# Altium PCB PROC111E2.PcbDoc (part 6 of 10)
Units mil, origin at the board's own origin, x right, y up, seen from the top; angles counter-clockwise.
Board outline 7700 x 2300 mil, 6 copper layers (Top Layer, GND 1, SIG 1, SIG 2, GND 2, Bottom Layer), stack 78.711 mil thick; 767 components, 596 nets, 2755 pads, 1578 vias.
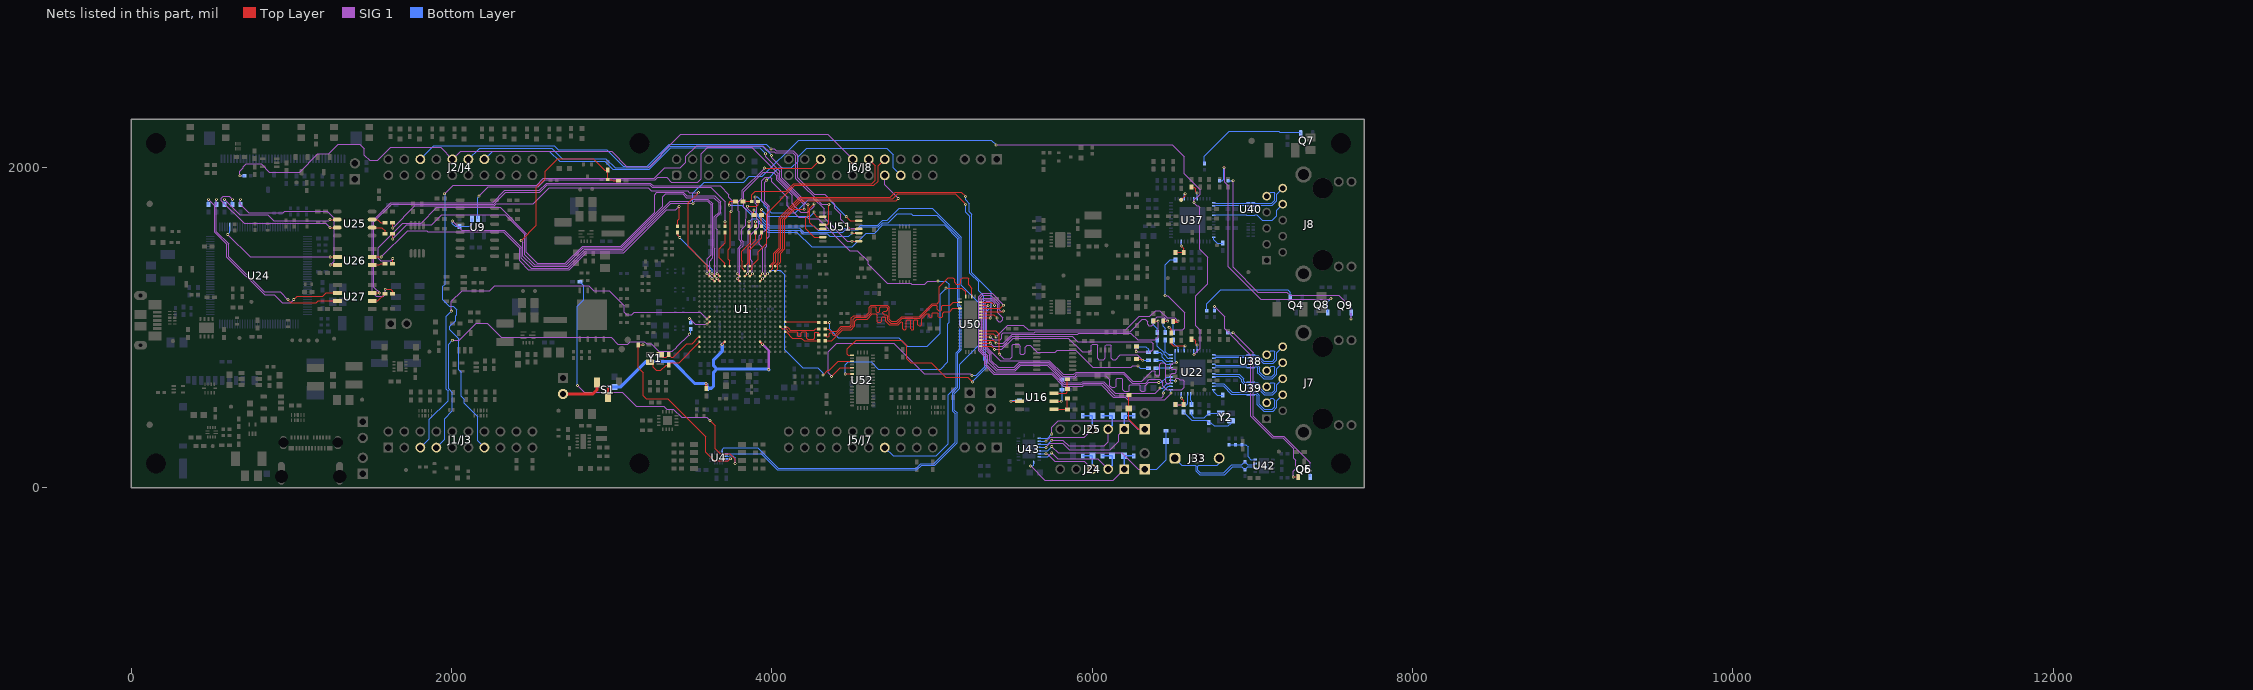
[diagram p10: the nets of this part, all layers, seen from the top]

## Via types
v1: diameter 18, hole 8, Top Layer to Bottom Layer, tented both sides, 1474 vias
v2: diameter 19.68, hole 7.87, Top Layer to Bottom Layer, tented both sides, 104 vias

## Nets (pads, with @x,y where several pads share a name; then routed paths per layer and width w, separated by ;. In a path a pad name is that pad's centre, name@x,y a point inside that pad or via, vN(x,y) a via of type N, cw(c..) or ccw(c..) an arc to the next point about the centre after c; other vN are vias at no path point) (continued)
AM263_RGMII1_TD2: R67.1 U50.25 | length 1428.5
  Top Layer w5.3: R67.1@4331.94,916.82 4373.56,916.82 4442.78,986.04 4494.62,986.04 4517.68,1009.1 4517.68,1039.31 4530.8,1052.44 4594.19,1052.44 4625.75,1084 4649.27,1084 4657.49,1075.78 4657.49,1036.99 4661.91,1032.57 4678.48,1032.57 4685,1039.09 4685,1059.57 4691.27,1065.83 4705.59,1065.83 4711.41,1060.02 4711.41,1038.55 4732.93,1017.03 4787.93,1017.03 4806.88,1035.98 4811.27,1035.98 4815.1,1032.15 4815.1,992.82 4821.94,985.98 4833.69,985.98 4838.47,990.75 4838.47,1040.1 4845,1046.63 4860,1046.63 4865,1041.63 4865,990.98 4870,985.98 4881.9,985.98 4885,989.08 4885,1041.63 4890,1046.63 4903.09,1046.63 4909.46,1040.27 4909.46,1018.34 4918.7,1009.1 4929.05,1009.1 4935.35,1015.4 4935.35,1054 4966.35,1085 4977.8,1085 4980.91,1081.9 4980.91,1066.49 4984.37,1063.04 4995.73,1063.04 5000.27,1067.58 5000.27,1087.35 5005,1092.09 5032.11,1092.09 5039.32,1084.88 5039.32,1067.71 5043.99,1063.04 5060,1063.04 5065.76,1068.79 5065.76,1089.06 5075.31,1098.62 5108.69,1098.62 5128.54,1118.46 U50.25@5173.43,1118.46
AM263_RGMII1_TD2_R: R67.2 U1.P18 | length 233.4
  Top Layer w5.3: U1.P18@4082.57,973.35 4087.82,973.35 4127.72,933.45 4184.23,933.45 4200.86,916.82 R67.2@4292.57,916.82
AM263_RGMII1_TD3: R68.1 U50.23 | length 1274
  Top Layer w5.3: R68.1@4331.94,952.82 4343.01,941.74 4352.79,941.74 4357.41,946.36 4357.41,961.57 4362.86,967.01 4374.36,967.01 4378.87,962.5 4378.87,955.3 4382.85,951.33 4393.08,951.33 4438.39,996.64 4490.22,996.64 4507.08,1013.49 4507.08,1051.3 4518.81,1063.04 4589.8,1063.04 4618.54,1091.78 4618.54,1122.48 4624.4,1128.34 4645,1128.34 4649.65,1123.69 4649.65,1100.31 4655.35,1094.6 4666.58,1094.6 4673.74,1101.76 4673.74,1122.08 4680,1128.34 4714.51,1128.34 4722.01,1120.84 4722.01,1110 4714.51,1102.5 4700,1102.5 4692.55,1095.05 4692.55,1087.55 4700.1,1080 4712.01,1080 4722.01,1070 4722.01,1046.11 4740.49,1027.63 4783.54,1027.63 4813.15,1057.23 4923.6,1057.23 5004.51,1138.15 5025,1138.15 5031.47,1131.67 5031.47,1113.66 5040.88,1104.25 5053.23,1104.25 5060,1111.03 5060,1133.15 5065,1138.15 5112.09,1138.15 5131.77,1157.83 U50.23@5173.43,1157.83
AM263_RGMII1_TD3_R: R68.2 U1.N17 | length 387.1
  Top Layer w4: U1.N17@4051.07,1004.84 4065.59,990.32
  Top Layer w5.3: 4065.59,990.32 4088.13,990.32 4105.96,972.49 4155,972.49 4161.05,966.45 4161.05,947.15 4164.15,944.05 4179.9,944.05 4183,947.15 4183,965.49 4190,972.49 4211.14,972.49 4218.5,965.14 4218.5,932.7 4223.78,927.42 4261.05,927.42 4268.07,934.44 4268.07,965.96 4271.18,969.06 4287.37,969.06 4292.57,963.87 R68.2@4292.57,952.82
AM263_RGMII1_TX_CTL: R69.1 U50.21 | length 1295
  Top Layer w5.3: R69.1@4331.94,1030.82 v1(4360,1030.82) ; v1(5087.15,1245.35) 5185.08,1245.35 5208.86,1221.57 U50.21@5208.86,1193.26
  Bottom Layer w5.3: v1(4360,1030.82) 4360,989.52 4414.52,935 4792.94,935 4845.53,882.4 4969.93,882.4 5050.6,963.07 5050.6,1208.8 v1(5087.15,1245.35)
AM263_RGMII1_TX_CTL_R: R69.2 U1.M18 | length 212.3
  Top Layer w5.3: U1.M18@4082.57,1036.34 4287.05,1036.34 R69.2@4292.57,1030.82
AM263_RGMII1_TXC: R70.1 U50.19 | length 1444
  Top Layer w5.3: R70.1@4331.94,989.82 4332.12,990 4355,990 4367.39,977.61 4404.37,977.61 4434,1007.24 4485.83,1007.24 4496.48,1017.88 4496.48,1059.94 4510.17,1073.64 4585.41,1073.64 4607.94,1096.17 4607.94,1127.68 4619.2,1138.94 4718.92,1138.94 4732.61,1125.25 4732.61,1050.5 4744.88,1038.23 4779.15,1038.23 4808.76,1067.83 4919.21,1067.83 5000.12,1148.75 5031.47,1148.75 5045.12,1162.4 5045.12,1255.39 5101.04,1311.31 5130,1311.31 5140.23,1301.08 5140.23,1282.14 5151.27,1271.09 5171.09,1271.09 5180,1280 5180,1301.31 5190,1311.31 5221.82,1311.31 5228.38,1304.75 5228.38,1266.01 5248.23,1246.17 U50.19@5248.23,1193.26
AM263_RGMII1_TXC_R: R70.2 U1.N18 | length 223
  Top Layer w4: U1.N18@4082.57,1004.84 4093.26,1004.84 4104.3,993.8
  Top Layer w5.3: 4104.3,993.8 4115,983.09 4264.3,983.09 4274.02,992.82 R70.2@4292.57,992.82
AM263_SAFETY_ERRORN: R258.1 R268.1 R272.1 U1.D4 | length 3081.6
  Top Layer w5.3: v1(2433.37,1542.21) 2529.29,1638.13 2529.29,1875.22 2583.47,1929.4 2583.47,1975.74 2661.47,2053.74 2884.26,2053.74 2956.06,1981.94 R258.1@2974.53,1981.94 2974.68,1981.79 R272.1@2974.68,1923.35 2975.04,1923.7 3000,1923.7 3008.24,1915.46 R268.1@3041.38,1915.46
  Top Layer w10: v1(3625.87,1304.06) U1.D4@3641.62,1288.31
  SIG 1 w4: 3610.87,1414.29 3610.87,1325.63 3625.87,1310.63 v1(3625.87,1304.06)
  SIG 1 w4.75: v1(2433.37,1542.21) 2445.05,1530.53 2445.05,1444.95 2509.04,1380.96 2724.9,1380.96 2831.89,1487.95 3064.45,1487.95 3365.07,1788.57 3489.88,1788.57 3502.41,1801.11 3600.33,1801.11 3630.27,1771.17 3630.27,1434.22 3610.87,1414.82 3610.87,1414.29
AM263_SD_ENABLE_GPIO122: U1.B16 U9.2 | length 3111.7
  Top Layer w4: U1.B16@4019.57,1351.3 4035.32,1367.05 4035.32,1390 4047.49,1402.17
  Top Layer w5.3: 4047.49,1402.17 4054.95,1409.63 4054.95,1464.39 4081.16,1490.6 4081.16,1675.53 4143.47,1737.85 v1(4201.68,1737.85)
  SIG 1 w4.75: v1(2170,1820) 2229.09,1879.09 2540.06,1879.09 2583.09,1922.12 3269.76,1922.12 3285.51,1937.87 3341.6,1937.87 3372.21,1907.27 3536.53,1907.27 3558.06,1928.8 3558.06,2085 3599.1,2126.04 3873.96,2126.04 4039.07,1960.93 4039.07,1927.47 4201.68,1764.86 v1(4201.68,1737.85)
  Bottom Layer w5.3: U9.2@2163.97,1678.43 2163.97,1810.55 2170,1816.58 v1(2170,1820)
AM263_SDFM0_CLK1: J6/J8.74 U1.A16 | length 1267.7
  Top Layer w5.3: U1.A16@4019.57,1382.8 4019.57,1387.4 4040,1407.83 4040,1464.43 4066.16,1490.59 4066.16,1675.52 4183,1792.36 4775.51,1792.36 v1(4788.5,1805.35)
  SIG 1 w5.3: J6/J8.74@4704.17,1950 4704.17,1889.68 v1(4788.5,1805.35)
AM263_SDFM0_CLK2: U1.B15 U52.26 | length 4090.4
  Top Layer w4: U1.B15@3988.08,1351.3 4005.7,1368.92 4005.7,1392.42 4015,1401.72
  Top Layer w5.3: 4015,1401.72 4025,1411.72 4025,1464.42 4055.56,1494.98 4055.56,1679.91 4178.61,1802.96 4752.96,1802.96 4784.76,1834.76 5143.4,1834.76 v1(5209.51,1768.66) ; v1(4372.19,693.86) 4372.19,696.09 4424.84,748.74 U52.26@4500.04,748.74
  SIG 1 w4.75: v1(4372.19,693.86) 4350,716.05 4350,849.04 4402.89,901.93 4760.56,901.93 4952,710.49 5237.09,710.49 5247.57,700 v1(5249.4,700)
  Bottom Layer w5.3: v1(5209.51,1768.66) 5209.51,1718.49 5234,1694 5234,1340.01 5290.12,1283.89 5290.12,1230.61 5322.88,1197.86 5322.88,795.76 5330,788.64 5330,754.57 5275.43,700 v1(5249.4,700)
AM263_SDFM0_CLK3: U1.A15 U52.22 | length 3872.2
  Top Layer w5.3: U1.A15@3988.08,1382.8 3988.08,1387.95 4010,1409.87 4010,1464.41 4044.35,1498.76 4044.35,1683.69 4174.22,1813.56 4738.56,1813.56 4770.36,1845.36 5182.8,1845.36 v1(5209.51,1818.66) ; U52.22@4500.04,827.48 4477.74,827.48 4471.48,833.74 4471.48,867.38 4525.54,921.45 4806.49,921.45 4842.94,885 4842.94,803.2 4867.11,779.03 4995.61,779.03 5084.52,690.11 5221.46,690.11 v1(5251.57,660)
  Bottom Layer w5.3: v1(5209.51,1818.66) 5209.51,1796.49 5232,1774 5232,1721.5 5247,1706.5 5247,1342 5369.52,1219.48 5369.52,1130.06 5333.48,1094.01 5333.48,800.15 5342.59,791.03 5342.59,751.02 v1(5251.57,660)
AM263_SDFM0_D2: U1.C13 U52.28 | length 3448.3
  Top Layer w5.3: v1(4457.78,709.37) U52.28@4500.04,709.37
  Top Layer w10: U1.C13@3925.09,1319.8 v1(3940.83,1335.55)
  SIG 1 w4: v1(3940.83,1335.55) 3940.83,1414.29
  SIG 1 w4.75: 3940.83,1414.29 3940.83,1499.17 3921.5,1518.5 3921.5,1571.78 3973.56,1623.84 3973.56,1752.64 3935.25,1790.95 3935.25,1915.6 3958.91,1939.25 3989.67,1939.25 3998.88,1930.04 3998.88,1909.72 4095.91,1812.69 4095.91,1759.11 4166.58,1688.45 4218.83,1688.45 4229.7,1677.58 4288.57,1677.58 4486.15,1480 4532.78,1480 4600.1,1412.68 4600.1,1395.57 4718.89,1276.77 4865.99,1276.77 4873.45,1269.3 4954.28,1269.3 4974.03,1289.06 v1@5036.55,1289.06
  Bottom Layer w5.3: v1(4457.78,709.37) 4457.78,766.95 4475.83,785 4619.38,785 4663.91,740.48 5053.89,740.48 5098.42,785 5098.42,1023.75 5106.67,1032.01 5106.67,1268.33 5085.59,1289.41 v1(5036.55,1289.41)
AM263_SDFM0_D3: U1.C14 U52.24 | length 1145.3
  Top Layer w5.3: v1(4318.59,702.78) 4349.11,733.31 4357.41,733.31 4412.22,788.11 U52.24@4500.04,788.11
  Top Layer w10: U1.C14@3956.58,1319.8 v1(3972.33,1335.55)
  Bottom Layer w5.3: v1(3972.33,1335.55) 3992.66,1355.88 4052.2,1355.88 4080.23,1327.84 4080.23,859.61 4191.46,748.38 4284.58,748.38 4318.59,714.37 v1(4318.59,702.78)
AM263_SFDM0_D1: J6/J8.73 U1.D13 | length 1729.1
  Top Layer w10: U1.D13@3925.09,1288.31 v1(3940.83,1304.06)
  SIG 1 w4: v1(3940.83,1304.06) 3957.33,1320.55 3957.33,1414.29
  SIG 1 w4.75: 3957.33,1414.29 3957.33,1496.33 3968,1507 3968,1554.28 3983.61,1569.89 3983.61,1756.81 3955,1785.42 3955,1908.12 v1(3966.88,1920)
  Bottom Layer w5.3: v1(3966.88,1920) 4042.66,1995.78 4121.38,1995.78 4163.14,2037.54 4163.14,2067 4216.01,2119.88 4717.44,2119.88 4757.29,2080.03 4757.29,1996.89 J6/J8.73@4804.17,1950
AM263_SOP0: R42.2 U4.15 | length 1162.8
  Top Layer w5.3: v1(3195,891.81) 3194.37,891.17 R42.2@3164.53,891.17 3164.53,748.79 3196.58,716.74 3196.58,573.42 3214.36,555.64 3348.26,555.64 3587.63,316.27 3587.63,219.09 3640,166.73 3726.88,166.73 v1(3740.06,179.91)
  Bottom Layer w5.3: U4.15@3713.32,179.91 v1(3740.06,179.91)
AM263_SOP1: R43.2 U4.14 | length 2060.4
  Top Layer w5.3: v1(3613.09,418.7) 3645.4,386.39 3645.4,243.33 3676.8,211.93 3735.65,211.93 3770,177.58 v1(3770,150)
  SIG 1 w4.75: v1(2785,638.11) 2828.96,594.15 3065,594.15 3151.87,507.27 3324.67,507.27 3342.27,489.68 3383.59,489.68 3435.04,438.22 3593.57,438.22 v1(3613.09,418.7)
  Bottom Layer w5.3: v1(2785,638.11) 2785,1131.61 2825,1171.61 2825,1260.61 R43.2@2800.61,1285 ; U4.14@3713.32,195.65 3728.2,195.65 3731.98,199.43 3756.37,199.43 3770,185.8 v1(3770,150)
AM263_SOP2: R173.2 U4.13 | length 4461.5
  Top Layer w5.3: R173.2@3886.97,1702.62 v1(3886.97,1733.21)
  Bottom Layer w5.3: U4.13@3713.32,211.4 3932.67,211.4 4034.07,110 4904.98,110 4934.38,139.4 5015.09,139.4 5155.35,279.65 5155.35,467.78 5138.73,484.4 5138.73,586.24 5171.62,619.13 5171.62,769.83 5289.73,887.94 5289.73,1153.66 5180.96,1262.44 5180.96,1564.13 5001.7,1743.39 4793.41,1743.39 4719.52,1669.5 4691.53,1669.5 4660.68,1638.65 4553.42,1638.65 4534.43,1619.65 4451.52,1619.65 4438.06,1606.19 4288.81,1606.19 4260.37,1634.64 3985.54,1634.64 v1(3886.97,1733.21)
AM263_SOP3: R174.2 U4.12 | length 4581.4
  Top Layer w5.3: v1(3733.14,1763.52) 3733.14,1779.8 3740,1786.65 R174.2@3771.82,1786.65
  Bottom Layer w5.3: U4.12@3689.69,219.28 3689.69,237.41 3699.69,247.41 3911.66,247.41 4038.46,120.6 4900.59,120.6 4929.99,150 5010,150 5144.52,284.52 5144.52,460.48 5128.13,476.87 5128.13,592.84 5160.6,625.31 5160.6,838.49 5183.1,860.98 5183.1,1125.25 5170.36,1137.99 5170.36,1559.74 5030.22,1699.88 4878.64,1699.88 4869,1709.52 4783.02,1709.52 4727,1653.5 4690.53,1653.5 4665.07,1628.05 4557.81,1628.05 4538.82,1609.05 4455.91,1609.05 4442.46,1595.59 4197.76,1595.59 4169.31,1624.04 3981.15,1624.04 3905.78,1699.41 3875.08,1699.41 3810.96,1763.52 v1(3733.14,1763.52)
AM263_SPI0_CLK: R169.1 R173.1 U51.2 | length 534.3
  Top Layer w5.3: v1(3934.21,1736.34) R173.1@3934.21,1702.62 3934.21,1632.95 R169.1@3935,1632.17 ; v1(4263.16,1720.73) 4263.16,1708.73 4280,1691.89 U51.2@4317.8,1691.89
  Bottom Layer w5.3: v1(3934.21,1736.34) 3974.91,1695.64 4238.07,1695.64 v1(4263.16,1720.73)
AM263_SPI0_CLK_PR0_PRU0_GPIO16: J1/J3.7 U51.4 | length 4690.4
  Top Layer w5.3: U51.4@4317.8,1640.71 4345.71,1640.71 4355,1650 v1(4355,1768.66)
  SIG 1 w4.75: v1(1954,1835) 1955.43,1835 2009.57,1889.14 2529.38,1889.14 2572.41,1932.17 3265.59,1932.17 3330.65,1997.22 3426.04,1997.22 3461.44,2032.63 3461.44,2067.7 3529.84,2136.09 3942.04,2136.09 3981.91,2096.22 4013.46,2096.22 4018.92,2090.76 4130.41,2090.76 4149.68,2071.49 4149.68,1929.92 4310.93,1768.66 v1(4355,1768.66)
  Bottom Layer w5.3: v1(1954,1835) 1958.18,1830.82 1958.18,1270.03 1944.52,1256.37 1944.52,1172.03 1984.79,1131.77 2010.16,1131.77 2030,1111.93 2030,1079.5 2024.06,1073.56 2024.06,1042.47 1988.42,1006.83 1988.42,985.61 2045.25,928.79 2045.25,736.04 2059.88,721.42 2059.88,570.48 2079.28,551.08 2079.28,526.21 2163.14,442.35 2163.14,291.04 J1/J3.7@2204.17,250
AM263_SPI0_CLK_R: R169.2 U1.A11 | length 240.2
  Top Layer w5.3: U1.A11@3862.09,1382.8 3862.09,1485.78 3935,1558.69 R169.2@3935,1592.8
AM263_SPI0_CS0: U1.C11 U51.14 | length 1317.9
  Top Layer w5.3: v1(4464,1691.89) 4489.59,1666.3 U51.14@4542.2,1666.3
  Top Layer w10: U1.C11@3862.09,1319.8 v1(3877.84,1335.55)
  SIG 1 w4: 3874.64,1414.29 3877.84,1411.09 v1(3877.84,1335.55)
  SIG 1 w4.75: 3874.64,1414.29 3866.86,1422.07 3866.86,1578.09 3916.25,1627.48 3916.25,1668.2 3906.22,1678.23 3906.22,1764.48 3894.94,1775.76 v1(3894.94,1815)
  Bottom Layer w5.3: v1(3894.94,1815) 3908.2,1815 3952.04,1771.17 3952.04,1761.12 3996.08,1717.08 4145.81,1717.08 4227.4,1798.67 4357.21,1798.67 v1(4464,1691.89)
AM263_SPI0_CS0_PR0_PRU0_GPIO8: J2/J4.18 U51.12 | length 3218.3
  Top Layer w5.3: v1(4464,1640.71) 4489.59,1615.12 U51.12@4542.2,1615.12
  SIG 1 w4.75: 4330.46,1830.85 4391.5,1769.82 4391.5,1745.5 4429.7,1707.3 4429.7,1675 v1(4464,1640.71)
  SIG 1 w5.3: v1(3993.13,2115.47) 4014.1,2115.47 4026.74,2102.83 4132.94,2102.83 4160,2075.77 4160,1934.19 4263.34,1830.85 4330.46,1830.85
  Bottom Layer w5.3: J2/J4.18@1804.17,2050 1889.17,2135 2640,2135 2665.89,2109.11 2969.11,2109.11 3070.33,2007.89 3222.13,2007.89 3359.23,2145 3963.61,2145 v1(3993.13,2115.47)
AM263_SPI0_D0: J6/J8.55 R170.1 R174.1 | length 1053.4
  Top Layer w5.3: R174.1@3819.07,1786.65 R170.1@3873.62,1786.65 3873.62,1828.88 3896.6,1851.85 4089.3,1851.85 4135.81,1898.36 4624.12,1898.36 4645.21,1919.45 4645.21,2008.96 J6/J8.55@4604.17,2050
AM263_SPI0_D0_R: R170.2 U1.C10 | length 559.8
  Top Layer w5.3: v1(3846.35,1756.91) 3904.46,1756.91 3912.99,1765.44 R170.2@3912.99,1786.65
  Top Layer w10: U1.C10@3830.6,1319.8 v1(3846.35,1335.55)
  SIG 1 w4: v1(3846.35,1335.55) 3846.35,1339.14 3850.91,1343.7 3850.91,1414.29
  SIG 1 w4.75: v1(3846.35,1756.91) 3846.35,1745 3876.25,1715.1 3876.25,1631.94 3850.91,1606.6 3850.91,1414.29
AM263_SPI0_D1: J6/J8.54 U1.B11 | length 1336.4
  Top Layer w4: U1.B11@3862.09,1351.3 3876.62,1365.82
  Top Layer w5.3: 3876.62,1365.82 3876.62,1389.62 3913.25,1426.24 3913.25,1472.59 3966.88,1526.23 3966.88,1711.16 4143.48,1887.76 4636.7,1887.76 4663.14,1914.2 4663.14,2008.96 J6/J8.54@4704.17,2050
AM263_SPI1_CLK: J5/J7.47 R171.1 | length 3214.5
  Top Layer w5.3: R171.1@3897,1632.17 v1(3897,1660.23)
  Bottom Layer w5.3: v1(3897,1660.23) 3909.62,1660.23 3974.99,1594.86 4155,1594.86 4247.08,1502.78 4501.02,1502.78 4587.24,1589 4641.02,1589 4692.87,1640.85 5074.26,1640.85 5159.76,1555.35 5159.76,1133.6 5172.5,1120.86 5172.5,865.37 5150,842.88 5150,630.01 5100,580.01 5100,272.8 5025.56,198.36 4755.81,198.36 J5/J7.47@4704.17,250
AM263_SPI1_CLK_R: R171.2 U1.A10 | length 237.5
  Top Layer w5.3: U1.A10@3830.6,1382.8 3851.19,1403.38 3851.19,1497.25 3897,1543.06 R171.2@3897,1592.8
AM263_SPI1_CS0: J6/J8.58 U1.C9 | length 1141.1
  Top Layer w5.3: v1(3953.46,1995.18) 4249.35,1995.18 J6/J8.58@4304.17,2050
  Top Layer w10: v1(3783.35,1335.55) U1.C9@3799.1,1319.8
  SIG 1 w4: v1(3783.35,1335.55) 3783.35,1339.14 3788.3,1344.09 3788.3,1414.29
  SIG 1 w4.75: 3788.3,1414.29 3788.3,1494.61 3809.25,1515.55 3809.25,1531.5 3794.5,1546.25 3794.5,1724.62 3790.75,1728.37 3790.75,1785.31 3814.95,1809.51 3814.95,1856.66 v1(3953.46,1995.18)
AM263_SPI1_D0: R172.1 U51.11 | length 776.2
  Top Layer w5.3: R172.1@3857,1632.17 v1(3857,1660.23) ; v1(4500,1589.53) U51.11@4542.2,1589.53
  Bottom Layer w5.3: v1(3857,1660.23) 3876.52,1679.75 3905.09,1679.75 3979.38,1605.46 4172.9,1605.46 4193.37,1584.99 4345,1584.99 4361.53,1568.46 4478.94,1568.46 v1(4500,1589.53)
AM263_SPI1_D0_PR0_PRU0_GPIO13: J2/J4.15 U51.9 | length 2897.4
  Top Layer w5.3: v1(4500,1538.35) U51.9@4542.2,1538.35
  SIG 1 w5.3: v1(3997.52,2074.18) 3997.52,2060.69 4060,1998.21 4060,1936.14 4185.98,1810.16 4254.83,1810.16 4325.26,1739.73 4325.26,1683.91 4470.83,1538.35 v1(4500,1538.35)
  Bottom Layer w5.3: J2/J4.15@2104.17,2050 2174.17,2120 2625,2120 2690,2055 2962.39,2055 3020.09,1997.29 3226.52,1997.29 3361.68,2132.45 3940.18,2132.45 3997.52,2075.11 v1(3997.52,2074.18)
AM263_SPI1_D0_R: R172.2 U1.B10 | length 274
  Top Layer w4: 3812.98,1414.29 3812.98,1368.92 U1.B10@3830.6,1351.3
  Top Layer w5.3: 3812.98,1414.29 3812.14,1415.13 3812.14,1475.98 3864.6,1528.44 3864.6,1585.2 R172.2@3857,1592.8
AM263_SPI1_D1: U1.D9 U51.5 | length 1498.9
  Top Layer w5.3: v1(4263.16,1771.81) 4236.08,1744.72 4236.08,1654.63 4275.59,1615.12 U51.5@4317.8,1615.12
  Top Layer w10: v1(3783.35,1304.06) U1.D9@3799.1,1288.31
  SIG 1 w4: v1(3783.35,1304.06) 3798.35,1319.06 3798.35,1414.29
  SIG 1 w4.75: 3798.35,1414.29 3798.35,1490.45 3819.3,1511.39 3819.3,1535.66 3810,1544.96 3810,1612 3835.5,1637.5 3835.5,1676 3840,1680.5 3840,1736.03 3825,1751.03 3825,1847.98 3946.42,1969.4 4007.1,1969.4 4029.02,1947.47 4029.02,1922.21 4126.06,1825.18 4126.06,1771.6 4179.07,1718.6 4224.16,1718.6 4263.16,1757.6 v1(4263.16,1771.81)
AM263_SPI1_D1_PR0_PRU0_GPIO14: J2/J4.14 U51.7 | length 2617.5
  Top Layer w5.3: v1(4225,1768.66) 4225,1699.19 4209.47,1683.66 4209.47,1617.63 4263.16,1563.94 U51.7@4317.8,1563.94
  SIG 1 w4.75: 4139.62,1841.52 4212.49,1768.66 v1(4225,1768.66)
  SIG 1 w5.3: v1(3960,2085) 3960,2065.82 4049.4,1976.43 4049.4,1931.75 4139.62,1841.52
  Bottom Layer w5.3: J2/J4.14@2204.17,2050 2255.81,2101.64 2608.36,2101.64 2673.33,2036.67 2955.83,2036.67 3005.81,1986.69 3233.69,1986.69 3368.85,2121.85 3923.15,2121.85 v1(3960,2085)
AM263_TCK: R324.1 U1.B3 | length 2631.6
  Top Layer w4: 3562.54,1418.51 3594.38,1386.67 3594.38,1367.05 U1.B3@3610.12,1351.3
  Top Layer w5.3: v1(1631.5,1620.83) R324.1@1631.5,1653.35 ; v1(3541.39,1842.03) 3476.63,1777.28 3476.63,1506.42 3562.54,1420.52 3562.54,1418.51
  SIG 1 w4.75: v1(1631.5,1620.83) 1770.28,1759.61 2265.99,1759.61 2278.18,1771.81 2508.64,1771.81 2608.7,1871.87 3228.06,1871.87 3246.19,1853.74 3472.88,1853.74 3484.59,1842.03 v1(3541.39,1842.03)
AM263_TCK_R: R324.2 U25.7 | length 90.4
  Top Layer w5.3: U25.7@1502.36,1673.86 1536.44,1673.86 1556.95,1653.35 R324.2@1584.25,1653.35
AM263_TCK_XDS: R133.1 U25.2 | length 795.1
  Top Layer w5.3: v1(1240,1673.86) U25.2@1285.36,1673.86
  SIG 1 w4.75: v1(580.73,1800) 675.73,1705 851.3,1705 889.42,1666.88 1233.02,1666.88 v1(1240,1673.86)
  Bottom Layer w5.3: R133.1@580.5,1767.63 580.5,1799.77 v1(580.73,1800)
AM263_TDI: R326.1 U1.C5 | length 3414.3
  Top Layer w5.3: R326.1@1631.5,1398.01 v1(1631.5,1430.54)
  Top Layer w10: v1(3657.37,1335.55) U1.C5@3673.12,1319.8
  SIG 1 w4: v1(3657.37,1335.55) 3657.37,1414.29
  SIG 1 w4.75: v1(1631.5,1430.54) 1618.09,1417.13 1555.65,1417.13 1540.75,1432.03 1540.75,1497.97 1692.9,1650.12 1808.12,1650.12 1907.56,1749.56 2301.91,1749.56 2465.15,1586.32 2465.15,1469.32 2533.41,1401.06 2710.03,1401.06 2817.47,1508.5 3055.8,1508.5 3267.56,1720.26 3267.56,1830 3281.25,1843.69 3445.5,1843.69 3467.99,1821.21 3641.7,1821.21 3679.24,1783.66 3679.24,1716.73 3650.37,1687.85 3650.37,1617.16 3657.37,1610.16 3657.37,1414.29
AM263_TDI_R: R326.2 U26.2 | length 84.3
  Top Layer w5.3: U26.2@1503.27,1390 1548.12,1390 1556.13,1398.01 R326.2@1584.25,1398.01
AM263_TDI_XDS: R135.1 U26.7 | length 1038.9
  Top Layer w5.3: v1(1241.37,1390) U26.7@1286.73,1390
  SIG 1 w4.75: v1(680.73,1800) 680.73,1767.91 733.03,1715.6 948.67,1715.6 957.59,1724.52 1222.37,1724.52 1265,1681.9 1265,1413.63 v1(1241.37,1390)
  Bottom Layer w5.3: R135.1@680.5,1767.63 680.5,1799.77 v1(680.73,1800)
AM263_TDO: R7.2 U26.3 | length 2423.5
  Top Layer w5.3: U26.3@1503.27,1440 v1(1560,1440) ; R7.2@3410,1632.17 3410,1668.5 3420,1678.5 v1(3420,1755.5)
  SIG 1 w4.75: v1(1560,1440) 1724.56,1604.56 1842.76,1604.56 1850,1597.32 2320.9,1597.32 2423.42,1494.8 2423.42,1415.12 2477.68,1360.86 2733.22,1360.86 2840.12,1467.76 3073.26,1467.76 3341.5,1736 3400.5,1736 v1(3420,1755.5)
AM263_TDO_R: R7.1 U1.C4 | length 368.9
  Top Layer w5.3: R7.1@3410,1592.8 3410.06,1592.74 3410.06,1576.14 v1(3424.12,1562.07)
  Top Layer w10: v1(3625.87,1335.55) U1.C4@3641.62,1319.8
  Bottom Layer w4: 3570.71,1414.29 3625.87,1359.13 v1(3625.87,1335.55)
  Bottom Layer w5.3: v1(3424.12,1562.07) 3424.12,1560.88 3570.71,1414.29
AM263_TDO_XDS: U24.37 U26.6 | length 796.7
  Top Layer w5.3: v1(1241.37,1440) U26.6@1286.73,1440
  SIG 1 w4.75: v1(601.14,1579.87) 741.01,1440 v1(1241.37,1440)
  Bottom Layer w5.3: v1(601.14,1579.87) 614.4,1593.13 U24.37@614.4,1627.52
AM263_TEMPCAL: U1.U1
AM263_TMS: R325.1 U1.D5 | length 3093.5
  Top Layer w5.3: v1(1631.5,1552.4) R325.1@1631.5,1584.92
  Top Layer w10: v1(3657.37,1304.06) U1.D5@3673.12,1288.31
  SIG 1 w4: 3642.37,1414.29 3642.37,1319.06 v1(3657.37,1304.06)
  SIG 1 w4.75: v1(1631.5,1552.4) 1719.17,1640.07 1874.63,1640.07 1936.81,1702.26 2335,1702.26 2455.1,1582.16 2455.1,1454.9 2518.99,1391.01 2714.2,1391.01 2821.64,1498.45 3059.96,1498.45 3319.02,1757.5 3319.02,1817.65 3335.01,1833.64 3441.34,1833.64 3463.83,1811.16 3637.53,1811.16 3669.19,1779.5 3669.19,1720.89 3640.32,1692.02 3640.32,1493.54 3642.37,1491.49 3642.37,1414.29
AM263_TMS_R: R325.2 U25.6 | length 109.2
  Top Layer w5.3: U25.6@1502.36,1623.86 1564.43,1623.86 1584.25,1604.05 R325.2@1584.25,1584.92
AM263_TMS_XDS: R134.1 U25.3 | length 925.6
  Top Layer w5.3: v1(1240,1623.86) U25.3@1285.36,1623.86
  SIG 1 w4.75: v1(630.73,1800) 610.73,1820 573.12,1820 560.7,1807.58 560.7,1792.42 703.12,1650 1213.86,1650 v1(1240,1623.86)
  Bottom Layer w5.3: R134.1@630.5,1767.63 630.5,1799.77 v1(630.73,1800)
AM263_UART0_RXD: R327.1 U1.A7 | length 3464
  Top Layer w4: U1.A7@3736.11,1382.8 3736.11,1414.29
  Top Layer w5.3: v1(1585,1238.85) 1618.09,1238.85 1631.5,1225.45 R327.1@1631.5,1210 ; 3736.11,1414.29 3736.11,1416.7 3726.25,1426.56 3726.25,1486.51 3740,1500.26 3740,1720 v1(3745,1725)
  SIG 1 w4.75: v1(1585,1238.85) 1585,1207.95 1573.07,1196.02 1529.25,1196.02 1503.89,1221.38 1503.89,1664.49 1619.11,1779.71 2255.44,1779.71 2332.59,1856.87 2546.9,1856.87 2592.05,1902.02 3240.56,1902.02 3257.48,1885.1 3675.32,1885.1 3730.75,1829.67 3730.75,1814.12 3752.39,1792.48 3752.39,1732.39 v1(3745,1725)
AM263_UART0_RXD_R: R327.2 U27.2 | length 99.5
  Top Layer w5.3: U27.2@1503.27,1165.27 1539.52,1165.27 R327.2@1584.25,1210
AM263_UART0_RXD_XDS: R131.1 U27.7 | length 1225
  Top Layer w5.3: v1(977.49,1173.93) 997.33,1154.09 1155,1154.09 ; 1155,1154.4 1155.32,1154.4 1166.18,1165.27 U27.7@1286.73,1165.27
  SIG 1 w4.75: v1(530.73,1800) 530.73,1598.86 607.1,1522.49 607.1,1442.9 828.18,1221.82 929.6,1221.82 v1(977.49,1173.93)
  Bottom Layer w5.3: R131.1@530.5,1767.63 530.5,1799.77 v1(530.73,1800)
AM263_UART0_TXD: R164.1 U27.3 | length 2991.7
  Top Layer w5.3: U27.3@1503.27,1215.27 v1(1550,1215.27) ; R164.1@3707,1632.17 v1(3707,1660.23)
  SIG 1 w4.75: v1(1550,1215.27) 1513.94,1251.33 1513.94,1658.94 1624.66,1769.66 2261.82,1769.66 2336.41,1844.25 2548.49,1844.25 2596.21,1891.97 3236.4,1891.97 3253.32,1875.05 3616.28,1875.05 3707,1784.33 v1(3707,1660.23)
AM263_UART0_TXD_R: R164.2 U1.A6 | length 241.4
  Top Layer w5.3: U1.A6@3704.61,1382.8 3704.61,1400.18 3669.34,1435.45 3669.34,1490.02 3708.39,1529.07 3708.39,1591.41 R164.2@3707,1592.8
AM263_UART0_TXD_XDS: R129.1 U27.6 | length 1275
  Top Layer w5.3: v1(1013.7,1173.93) 1035.48,1195.71 1195.71,1195.71 1215.27,1215.27 U27.6@1286.73,1215.27
  SIG 1 w4.75: v1(480.73,1800) 520.13,1760.6 520.13,1594.47 596.5,1518.1 596.5,1438.51 831.18,1203.83 891.41,1203.83 940.83,1154.41 994.18,1154.41 v1(1013.7,1173.93)
  Bottom Layer w5.3: R129.1@480.5,1767.63 480.5,1799.77 v1(480.73,1800)
AM263_UART1_RXD: J1/J3.3 U1.L3 | length 2783.2
  Top Layer w10: v1(3594.38,1052.09) U1.L3@3610.12,1067.83
  SIG 1 w4.75: v1(1997.69,1101.65) 1997.69,1162.66 2064.46,1229.44 2237.21,1229.44 2268.14,1260.36 2855.42,1260.36 2887.28,1228.5 2984.8,1228.5 3078.21,1135.09 3078.21,1095 3093.21,1080 3125.39,1080 3140.39,1095 3551.46,1095 v1(3594.38,1052.09)
  Bottom Layer w5.3: J1/J3.3@1804.17,250 1860,305.83 1860,426.72 1976.8,543.51 1976.8,604.62 1966.24,615.18 1966.24,1070.2 v1(1997.69,1101.65)
AM263_UART1_TXD: J1/J3.4 R165.1 | length 2422
  SIG 1 w4.75: v1(2004.02,919.76) 2045.73,919.76 2152.38,1026.42 2221.36,1026.42 2309.83,937.95 2995.7,937.95 3038.23,895.42 3097.69,895.42 3113.32,911.06 3202.97,911.06 3216.83,897.2 3246.37,897.2 3292.87,850.7 3378.14,850.7 3405.31,877.88 3405.31,878.5 v1(3485,958.19)
  Bottom Layer w5.3: J1/J3.4@1904.17,250 1955,300.83 1955,431.22 2004.54,480.76 2004.54,591.87 1980.4,616.02 1980.4,896.14 v1(2004.02,919.76) ; v1@3485,957.6 3492.19,964.79 R165.1@3492.19,989.72
AM263_UART1_TXD_R: R165.2 U1.M3 | length 177.1
  Top Layer w10: v1(3594.38,1020.59) U1.M3@3610.12,1036.34
  SIG 1 w5.3: v1(3484.5,1056.16) 3520.07,1020.59 v1(3594.38,1020.59)
  Bottom Layer w5.3: v1(3484.5,1056.16) 3492.19,1048.47 R165.2@3492.19,1029.09
AM263_WARMRSTN: R5.2 U1.C3 U9.1 U22.43 U37.43 | length 7360.7
  Top Layer w10: v1(3594.38,1335.55) U1.C3@3610.12,1319.8
  SIG 1 w4: v1(3594.38,1335.55) 3594.38,1408.67
  SIG 1 w4.75: v1(2004.02,1665) 2061.65,1607.37 2327.48,1607.37 2435,1499.85 2435,1432.68 2496.77,1370.91 2729.06,1370.91 2835.96,1477.81 3069.1,1477.81 3366.29,1775 v1(3506.1,1775) 3522.16,1791.06 3596.17,1791.06 3620.22,1767 3620.22,1453.81 3594.38,1427.97 3594.38,1408.67 ; v1(5400,2140) 6500,2140 6575,2065 6575,1960.02 6674.25,1860.77 6674.25,1832.03 6635.02,1792.8 v1(6635.02,1779.98) 6654,1761 6660.47,1761 6672.23,1749.23 6672.23,1488.26 6721.09,1439.41 6721.09,1271.92 6646.97,1197.79 6646.97,1010.2 6674.25,982.92 6674.25,869.21 v1(6635.02,829.98)
  Bottom Layer w5.3: v1(2004.02,1665) 2004.02,1648.05 2021.02,1631.04 R5.2@2048.11,1631.04 2111.04,1631.04 2126.56,1646.56 U9.1@2126.56,1678.43 ; v1(3506.1,1775) 3506.1,1837.38 3575.71,1907 3823.22,1907 3859.52,1943.29 3939.43,1943.29 4165.66,2169.52 5370.48,2169.52 v1(5400,2140) ; v1(6635.02,829.98) U22.43@6635.02,853.9 ; v1(6635.02,1779.98) U37.43@6635.02,1803.9
AM263_XTAL_XI: C58.1 U1.T1 Y1.1 | length 416.1
  Top Layer w5.3: Y1.1@3238.01,782.59 3242.89,782.59 3256.98,768.51 3256.98,751.63 3276.91,731.69 3305.48,731.69 3338.34,764.56 3354.72,764.56 C58.1@3355,764.84 3369.27,779.1 3419.37,779.1 3547.13,906.87 U1.T1@3547.13,910.35
AM263_XTAL_XO: C59.1 U1.R1 Y1.3 | length 317.9
  Top Layer w5.3: Y1.3@3301.99,829.84 3317.42,814.4 3338.69,814.4 C59.1@3355,830.71 3371.4,814.32 3383.73,814.32 3467.98,898.57 3500.62,898.57 3539.63,937.58 3542.86,937.58 U1.R1@3547.13,941.85
BP_PORZ: J2/J4.16 J6/J8.56 R180.2 | length 4344.6
  SIG 1 w4.75: v1(677.39,1947.24) 677.39,1974.61 699.25,1996.47 699.25,2005 716.59,2022.34 809.83,2022.34 861.41,1970.75 1051.07,1970.75 1164.32,2084 1232.5,2084 1292,2143.5 1425,2143.5 1453.75,2114.75 1453.75,2076.75 1487.5,2043 1538.83,2043 1620,2124.17 1930,2124.17 J2/J4.16@2004.17,2050 2055.53,2101.36 2390,2101.36
  SIG 1 w5.3: 2390,2101.36 2997.77,2101.36 3094.28,2004.85 3237.63,2004.85 3308.06,2075.28 3308.06,2085.77 3429.01,2206.72 4347.45,2206.72 J6/J8.56@4504.17,2050
  Bottom Layer w5.3: v1(677.39,1947.24) 677.47,1947.32 R180.2@706,1947.32
CAN_STB: R244.1 R248.1 R250.2 U42.8 | length 238
  Bottom Layer w5.3: R248.1@6855,267.87 R250.2@6895,267.87 R244.1@6935,267.87 6960,267.87 6973.16,254.71 6973.16,191.84 6990.16,174.84 U42.8@7017.68,174.84
CANA_N: J33.1 R246.2 U42.6 | length 601.7
  Bottom Layer w4.1: J33.1@6516.38,183.86 6559.77,140.47 6642.64,140.47 6648.72,134.38 6648.72,103.22 6670.48,81.46 6826.84,81.46 6876.39,131.01 6933.25,131.01 R246.2@6952.8,111.46 6972.35,131.01 7004.62,131.01 7011.97,123.66 U42.6@7017.68,123.66
CANA_P: J33.3 R247.2 U42.7 | length 601.6
  Bottom Layer w4.1: J33.3@6791.97,183.86 6791.97,152.58 6779.86,140.47 6666.4,140.47 6659.62,133.69 6659.62,107.74 6675,92.36 6822.33,92.36 6871.87,141.91 6933.25,141.91 R247.2@6952.8,161.46 6972.35,141.91 7004.62,141.91 7011.97,149.25 U42.7@7017.68,149.25
DAC_EXT_VREF: J18.2 S1.3 | length 268.8
  Top Layer w20: J18.2@2695,584.47 2881.59,584.47 2906.71,609.58 S1.3@2906.71,656.22
DAC_VREF: C89.1 C90.1 C91.1 S1.2 U1.T6 U1.T13 | length 1758.8
  Top Layer w15: S1.2@2975.61,565.67 v1(2975.61,629.98) ; v1(3587.63,650) 3590,647.63 C91.1@3590,618.62 ; v1(3688.87,894.61) U1.T6@3704.61,910.35 ; U1.T13@3925.09,910.35 v1(3940.83,894.61)
  SIG 1 w15: v1(3940.83,894.61) 3980.05,855.39 3980,855.33 v1(3980,736.35)
  Bottom Layer w20: v1(2975.61,629.98) 2975.61,629.34 2976.45,628.5 C89.1@3015,628.5 3015,628.64 3055,628.64 3214.51,788.15 3379.55,788.15 3517.7,650 v1(3587.63,650) 3595,642.63 C90.1@3595,618.53 3596.18,619.71 3620.8,619.71 3635.58,634.49 3635.58,720.95 3655.1,740.48 ; v1(3688.87,894.61) 3688.87,852.61 3635.58,799.32 3635.58,760 3655.1,740.48 ; v1(3980,736.35) 3976.4,739.95 3655.62,739.95 3655.1,740.48
EEPROM_A0: R318.2 R321.2 U16.1 | length 154.4
  Top Layer w5.3: U16.1@5760.08,489.14 5844.38,489.14 R318.2@5845.31,488.21 R321.2@5845.31,556.99
EEPROM_A1: R319.2 R322.2 U16.2 | length 184.1
  Top Layer w5.3: U16.2@5760.08,539.14 v1(5806.02,539.14)
  Bottom Layer w5.3: v1(5806.02,539.14) 5811.68,544.81 R322.2@5811.68,611.02 R319.2@5811.68,675
EEPROM_A2: R320.2 R323.2 U16.3 | length 167.7
  Top Layer w5.3: U16.3@5760.08,589.14 5836.53,589.14 5845.31,597.92 R323.2@5845.31,615 R320.2@5845.31,676.73
EEPROM_WP: R316.1 U16.7 | length 110.1
  Top Layer w5.3: v1(5492.11,539.14) U16.7@5545.51,539.14
  Bottom Layer w5.3: v1(5492.11,539.14) 5498.01,545.04 R316.1@5546.38,545.04
EQEP0_A: C214.1 J24.1 R236.1 U43.20 | length 828.4
  SIG 1 w4.75: v1(5615,135) 5702.83,47.17 6131.34,47.17 J24.1@6199.18,115
  Bottom Layer w5.3: v1(5615,135) 5615.09,135.09 5628.28,135.09 5633.19,140 U43.20@5633.19,155.98
  Bottom Layer w10: J24.1@6199.18,115 C214.1@6199.18,198.5 R236.1@6259.18,198.5
EQEP0_B: C215.1 J24.2 R237.1 U43.18 | length 637.3
  SIG 1 w4.75: v1(5746.83,217) 5783.83,180 6034.18,180 J24.2@6099.18,115
  Bottom Layer w5.3: U43.18@5668.62,191.41 5721.24,191.41 v1(5746.83,217)
  Bottom Layer w10: R237.1@6064.18,198.5 C215.1@6124.18,198.5 6124.18,140 J24.2@6099.18,115
EQEP0_INDEX: C216.1 J24.3 R238.1 U43.17 | length 514.2
  SIG 1 w4.75: v1(5710.83,211.1) 5713.26,208.67 5721.33,208.67 5765,165 5949.18,165 J24.3@5999.18,115
  Bottom Layer w5.3: U43.17@5668.62,211.1 v1(5710.83,211.1)
  Bottom Layer w10: R238.1@5940,198.5 C216.1@6000,198.5 6000,115.82 J24.3@5999.18,115
EQEP0_STROBE: C220.1 J15.1 R242.1 U43.16 | length 1068.2
  SIG 1 w5.3: v1(5746.83,256.37) 5786.2,217 6184.58,217 6286.58,115 J15.1@6327.06,115
  Bottom Layer w5.3: U43.16@5668.62,230.78 5721.24,230.78 v1(5746.83,256.37) ; J15.1@6327.06,115 6402.9,115 6460.67,172.77 C220.1@6460.67,290.82 6461.51,291.66 R242.1@6461.51,355.53
EQEP2_A: C217.1 J25.1 R239.1 U43.15 | length 777.5
  SIG 1 w4.75: v1(5710.83,250.47) 5735.98,275.62 5816.23,275.62 5855,236.85 6111.85,236.85 6165,290 6165,330.82 J25.1@6199.18,365
  Bottom Layer w5.3: U43.15@5668.62,250.47 v1(5710.83,250.47)
  Bottom Layer w10: J25.1@6199.18,365 C217.1@6199.18,448.5 R239.1@6259.18,448.5
EQEP2_B: C218.1 J25.2 R240.1 U43.14 | length 700.2
  SIG 1 w4.75: v1(5746.83,295.74) 5816.12,295.74 5851.86,260 6074.18,260 6099.18,285 J25.2@6099.18,365
  Bottom Layer w5.3: U43.14@5668.62,270.15 5721.24,270.15 v1(5746.83,295.74)
  Bottom Layer w10: R240.1@6064.18,448.5 C218.1@6124.18,448.5 6124.18,390 J25.2@6099.18,365
EQEP2_INDEX: C219.1 J25.3 R241.1 U43.13 | length 505.8
  SIG 1 w4.75: v1(5710.83,289.84) 5736.25,315.27 5754.91,315.27 5755.18,315 5949.18,315 J25.3@5999.18,365
  Bottom Layer w5.3: U43.13@5668.62,289.84 v1(5710.83,289.84)
  Bottom Layer w10: R241.1@5940,448.5 C219.1@6000,448.5 6000,365.82 J25.3@5999.18,365
EQEP2_STROBE: C221.1 J16.1 R243.1 U43.12 | length 1026.2
  Top Layer w5.3: R243.1@6228.62,578.2 C221.1@6228.62,494.67 6228.62,426.16 6289.78,365 J16.1@6327.06,365
  SIG 1 w5.3: v1(5746.83,335.11) 5746.83,376.91 5788.61,418.7 6230,418.7 6283.7,365 J16.1@6327.06,365
  Bottom Layer w5.3: U43.12@5668.62,309.52 5721.24,309.52 v1(5746.83,335.11)
ETH1_CLKOUT: R106.2 R213.1 | length 681.7
  Top Layer w5.3: v1(6480,1001.54) 6492.48,989.06 6492.48,964.89 R106.2@6493.31,964.06
  SIG 1 w5.3: v1(6455,1198.82) 6470.65,1198.82 6578.11,1091.35 6578.11,999.23 6564.36,985.48 6496.06,985.48 v1(6480,1001.54)
  Bottom Layer w5.3: v1(6455,1198.82) 6456.28,1200.09 6456.28,1390.04 6487.61,1421.38 R213.1@6520,1421.38
ETH1_CLKOUT_R: R106.1 U22.40 | length 143.4
  Top Layer w5.3: R106.1@6493.31,916.82 6493.31,898.47 6506.77,885 v1(6580,885)
  Bottom Layer w5.3: U22.40@6575.96,853.9 6575.96,880.96 v1(6580,885)
ETH1_GPIO_1: R114.1 R126.2 U22.22 | length 124.8
  Top Layer w5.3: R114.1@6520,518.62 R126.2@6570.85,518.62 6570.97,518.5 6570.97,543.56 v1(6556.28,558.25)
  Bottom Layer w5.3: v1(6556.28,558.25) U22.22@6556.28,586.18
ETH1_LED0: Q5.1 R227.1 | length 1377.5
  Top Layer w5.3: v1(7255,66.42) Q5.1@7286.6,66.42
  SIG 1 w5.3: v1(6762.73,1131.46) 6825.85,1068.34 6825.85,991.55 6990,827.4 6990,445.22 7124.89,310.33 7190,310.33 7257.23,243.1 7257.23,181.91 7269.52,169.62 7269.52,117.13 7255,102.61 v1(7255,66.42)
  Bottom Layer w5.3: R227.1@6762.73,1104.68 v1(6762.73,1131.46)
ETH1_LED1: Q6.1 R229.1 | length 1171.5
  SIG 1 w5.3: v1(6880,966.71) 7005,841.71 7005,445.21 7129.28,320.92 7194.39,320.92 7360,155.32 v1(7360,105)
  Bottom Layer w5.3: R229.1@6846.59,967.35 6879.36,967.35 v1(6880,966.71) ; v1(7360,105) 7361.4,103.6 Q6.1@7361.4,66.42
ETH1_LED2: Q4.1 R225.1 | length 639.7
  Bottom Layer w5.3: R225.1@6715,1104.31 6715,1148.44 6801.44,1234.88 7220.44,1234.88 7236.69,1218.62 Q4.1@7236.69,1187.24
ETH1_PWDN: R305.2 U22.44 | length 96.3
  Top Layer w5.3: R305.2@6620,926.46 6635.61,926.46 6647.07,915 6647.07,897.93 v1(6655,890)
  Bottom Layer w5.3: U22.44@6654.7,853.9 6654.7,889.7 v1(6655,890)
ETH1_RBIAS: R107.2 U22.12 | length 78.8
  Bottom Layer w5.3: U22.12@6759.03,611.77 6759.03,597.39 6779.43,576.99 R107.2@6815,576.99
ETH1_RD0: R102.1 R108.1 R120.2 U50.2 | length 1562.3
  Top Layer w5.3: U50.2@5303.35,882.24 5370.31,882.24 v1(5390,862.56) ; R108.1@6274.92,802.65 6307.35,802.65 v1(6315,795)
  SIG 1 w4.75: v1(5390,862.56) 5434.78,862.56 5506.27,934.04 5849.85,934.04 5936.89,847 5984.43,847 5995,857.58 5995,887.63 6002.37,895 6027,895 6033.5,888.5 6033.5,808 6042,799.5 6072,799.5 6082.5,810 6082.5,884.31 6090,891.81 6111.9,891.81 6118.31,885.4 6118.31,807.56 6127.58,798.29 6145.75,798.29 6175.76,828.31 6281.69,828.31 v1(6315,795)
  Bottom Layer w5.3: R120.2@6274.92,802.65 6305.55,802.65 6313.2,795 v1(6315,795) ; v1(6315,795) v1(6315,795) ; v1(6315,795) v1(6315,795) ; v1(6315,795) R102.1@6351.89,795.04 v1(6315,795)
ETH1_RD0_R: R102.2 U22.33 | length 102.9
  Bottom Layer w5.3: R102.2@6399.14,795.04 6434.21,795.04 6460,769.25 U22.33@6491.32,769.25
ETH1_RD1: R103.1 R109.1 R121.2 U50.3 | length 1441.6
  Top Layer w5.3: U50.3@5303.35,901.93 v1(5363,901.93) ; v1(6274.92,848.96) 6275,849.04 R109.1@6275,880.96
  SIG 1 w4.75: v1(5363,901.93) 5382.25,882.68 5440.3,882.68 5501.72,944.09 5875.18,944.09 5910,909.28 6367.65,909.28 6380,896.93 6380,862.58 6366.39,848.96 v1(6274.92,848.96)
  Bottom Layer w5.3: v1(6274.92,848.96) 6275,849.04 6275,880.96 R121.2@6275.11,880.85 6335,880.85 6351.89,863.96 R103.1@6351.89,845.04
ETH1_RD1_R: R103.2 U22.34 | length 126.8
  Bottom Layer w5.3: R103.2@6399.14,845.04 6399.18,845 6425.16,845 6438.01,832.15 6438.01,812.74 6461.81,788.94 U22.34@6491.32,788.94
ETH1_RD2: R104.1 R115.1 R127.2 U50.4 | length 1405.3
  Top Layer w5.3: U50.4@5303.35,921.61 5380.31,921.61 v1(5400,901.93) ; R115.1@6383.01,1039.34 6411.64,1039.34 v1(6411.73,1039.27)
  SIG 1 w4.75: v1(5400,901.93) 5444.28,901.93 5500,957.65 5910.18,957.65 5916.61,964.08 6240.92,964.08 6283.23,921.77 6394.93,921.77 6411.73,938.57 v1(6411.73,1039.27)
  Bottom Layer w5.3: R104.1@6406.28,968.62 6406.28,990.72 6383.01,1013.99 6383.01,1039.35 6411.65,1039.35 v1(6411.73,1039.27)
ETH1_RD2_R: R104.2 U22.35 | length 159.3
  Bottom Layer w5.3: R104.2@6406.28,921.38 6406.28,883.72 6448.61,841.39 6448.61,831.98 6471.97,808.62 U22.35@6491.32,808.62
ETH1_RD3: R105.1 R116.1 R128.2 U50.5 | length 1451.1
  Top Layer w5.3: U50.5@5303.35,941.3 v1(5363,941.3) ; R116.1@6443.01,1039.35 v1(6471.73,1039.27) v1(6471.73,1039.27)
  SIG 1 w4.75: v1(5363,941.3) 5382.52,921.77 5425,921.77 5435,931.77 5435,959.08 5443.62,967.7 5638.89,967.7 5645.32,974.13 6213.36,974.13 6237.72,974.13 6313.59,1050 6329.53,1050 6345,1034.53 6345,1019.23 6354.23,1010 6370.2,1010 6380,1019.8 6380,1040.56 6405.24,1065.8 6445.2,1065.8 v1(6471.73,1039.27)
  Bottom Layer w5.3: R105.1@6456.28,968.62 6456.28,993.72 6443.01,1006.99 R128.2@6443.01,1039.35 v1(6471.73,1039.27) v1(6471.73,1039.27)
ETH1_RD3_R: R105.2 U22.36 | length 116.2
  Bottom Layer w5.3: R105.2@6456.28,921.38 6456.28,848.71 6476.68,828.31 U22.36@6491.32,828.31
ETH1_RX_CTL: R101.1 R113.1 R125.2 U50.6 | length 1489.3
  Top Layer w5.3: U50.6@5303.35,960.98 5380.31,960.98 v1(5400,941.3)
  Top Layer w15: R113.1@6506.28,1036.06 6530.9,1036.06 6534.27,1039.43 6534.92,1039.43 v1(6535,1039.35)
  SIG 1 w4.75: v1(5400,941.3) 5471.99,1013.28 5570,1013.28 5599.1,984.18 5740,984.18 6209.2,984.18 6293.59,1068.57 6360,1068.57 6397.19,1105.76 6421.29,1105.76 6467.71,1059.35 6515,1059.35 v1(6535,1039.35)
  Bottom Layer w5.3: R101.1@6506.28,968.62 R125.2@6506.28,1036.06 6506.28,1039.43 6534.92,1039.43 v1(6535,1039.35)
ETH1_RX_CTL_R: R101.2 U22.38 | length 80
  Bottom Layer w5.3: R101.2@6506.28,921.38 6506.28,902.66 6536.59,872.35 U22.38@6536.59,853.9
ETH1_RXC: R100.1 U50.7 | length 1448.9
  Top Layer w5.3: U50.7@5303.35,980.67 5395.9,980.67 5420,956.57 v1(5420,833.39)
  SIG 1 w4.75: v1(5420,833.39) 5448.39,805 5487.57,805 5499.83,817.26 5499.83,888.13 5506.7,895 5540,895 5550.88,884.12 5550.88,836.51 5555,832.4 5573.7,832.4 5582.03,840.72 5582.03,876.84 5595.19,890 5611.43,890 5657.06,844.36 5769.87,844.36 5782.78,857.27 5898.2,857.27 6003.99,751.48 6244.48,751.48 6253,760 v1(6285.22,760)
  Bottom Layer w5.3: v1(6285.22,760) 6300.18,745.04 R100.1@6351.89,745.04
ETH1_RXC_R: R100.2 U22.32 | length 94.1
  Bottom Layer w5.3: R100.2@6399.14,745.04 6403.66,749.57 U22.32@6491.32,749.57
ETH1_TD0: U22.28 U50.11 | length 2084.4
  Top Layer w5.3: U50.11@5303.35,1059.41 v1(5363,1059.41)
  SIG 1 w4.75: v1(5363,1059.41) 5363,1061.06 5370.75,1068.81 5370.75,1149.62 5357.34,1163.03 5342.66,1163.03 5330.75,1151.12 5330.75,873.2 5368.7,835.25 5368.7,793.58 5412.14,750.14 5512.16,750.14 5545.16,783.13 5727.91,783.13 5814.73,696.31 5890,696.31 5903.54,709.85 6192.9,709.85 6249.72,653.03 6333.71,653.03 6356.4,675.72 6422.97,675.72 6440,658.7 6440,635 6465,610 6560,610 6575,625 6575,663.08 6565.1,672.98 6545.99,672.98 6535.73,683.24 6525,683.24 6520.03,678.27 v1(6520,665)
  Bottom Layer w5.3: U22.28@6491.32,670.83 6514.17,670.83 v1(6520,665)
ETH1_TD1: U22.27 U50.12 | length 2082.8
  Top Layer w5.3: U50.12@5303.35,1079.09 5386.14,1079.09 v1(5405.83,1059.41)
  SIG 1 w4.75: v1(5405.83,1059.41) 5405.83,1046.1 5415,1036.93 5428.31,1036.93 5440,1048.61 5440,1060.24 5409.52,1090.71 5409.52,1145.84 5372.24,1183.13 5320.28,1183.13 5310.65,1173.51 5310.65,862.02 5348.6,824.07 5348.6,781.4 5399.96,730.04 5520.49,730.04 5553.06,762.62 5720,762.62 5828.62,654 5932.11,654 5939.11,661 6071.8,661 6142.8,590 6392.27,590 v1(6423.51,621.24)
  Bottom Layer w5.3: v1(6423.51,621.24) 6439.75,621.24 6469.65,651.14 U22.27@6491.32,651.14
ETH1_TD2: U22.26 U50.13 | length 2083
  Top Layer w5.3: U50.13@5303.35,1098.78 5440.96,1098.78 v1(5444.69,1102.5)
  SIG 1 w4.75: v1(5444.69,1102.5) 5427.5,1102.5 5420,1110 5420,1149.11 5419.57,1149.54 5419.57,1150.01 5367.01,1202.57 5316.69,1202.57 5300.6,1186.48 5300.6,857.86 5338.55,819.91 5338.55,771.45 5391.78,718.22 5635.41,718.22 5637.22,716.41 5749.75,716.41 5822.21,643.95 5936.27,643.95 5943.27,650.95 6064.05,650.95 6140.7,574.3 6211.31,574.3 6225.56,560.05 6435.05,560.05 6444.47,569.47 v1(6444.47,590.85)
  Bottom Layer w5.3: v1(6444.47,590.85) 6444.47,600.71 6475.21,631.46 U22.26@6491.32,631.46
ETH1_TD3: U22.25 U50.14 | length 2084.3
  Top Layer w5.3: U50.14@5303.35,1118.46 5424.41,1118.46 v1(5444.69,1138.73)
  SIG 1 w4.75: v1(5444.69,1138.73) 5444.69,1142.55 5374.62,1212.62 5311.94,1212.62 5290.55,1191.23 5290.55,853.7 5328.5,815.75 5328.5,765.79 5386.11,708.17 5631.25,708.17 5633.06,706.36 5745.58,706.36 5818.05,633.9 5940.44,633.9 5947.44,640.9 6055.5,640.9 6132.15,564.25 6207.15,564.25 6221.4,550 6452.17,550 v1(6492.17,590)
  Bottom Layer w5.3: U22.25@6491.32,611.77 6491.32,590.85 v1(6492.17,590)
ETH1_TD_A_N: J7.10 U22.2 U38.2 U38.9 | length 517.6
  Bottom Layer w4: U22.2@6759.03,808.62 6766.12,808.62 6770.11,812.61 6960.13,812.61 6964.12,808.62 U38.9@6973.14,808.62 U38.2@7006.02,808.62 7013.2,808.62 7017.19,812.61 7032.5,812.61 7067.37,777.74 7130.85,777.74 7152.19,799.09 7152.19,843.12 J7.10@7189.08,880
ETH1_TD_A_P: J7.9 U22.1 U38.1 U38.10 | length 515.8
  Bottom Layer w4: U22.1@6759.03,828.31 6766.12,828.31 6770.11,824.31 6960.13,824.31 6964.12,828.31 U38.10@6973.14,828.31 U38.1@7006.02,828.31 7013.2,828.31 7017.19,824.31 7037.35,824.31 7072.22,789.44 7126.01,789.44 7140.49,803.93 7140.49,848.4 7133.9,855 7114.08,855 J7.9@7089.08,830
ETH1_TD_B_N: J7.8 U22.5 U38.5 U38.6 | length 546.8
  Bottom Layer w4: U22.5@6759.03,749.57 6766.12,749.57 6770.11,753.56 6944.85,753.56 6961.96,753.56 6965.96,749.57 U38.6@6973.14,749.57 U38.5@7006.02,749.57 7013.2,749.57 7017.19,753.56 7026.59,753.56 7035,745.15 7035,715.15 7041.51,708.64 7071.12,679.04 7124.85,679.04 7152.19,706.39 7152.19,743.12 J7.8@7189.08,780
ETH1_TD_B_P: J7.7 U22.4 U38.4 U38.7 | length 547.5
  Bottom Layer w4: U22.4@6759.03,769.25 6766.12,769.25 6770.11,765.26 6940,765.26 6961.96,765.26 6965.96,769.25 U38.7@6973.14,769.25 U38.4@7006.02,769.25 7013.2,769.25 7017.19,765.26 7031.44,765.26 7046.7,750 7046.7,720 7053.21,713.49 7075.96,690.74 7120,690.74 7140.49,711.23 7140.49,749.07 7132.02,757.54 7116.62,757.54 J7.7@7089.08,730
ETH1_TD_C_N: J7.6 U22.8 U39.2 U39.9 | length 568.2
  Bottom Layer w4: U22.8@6759.03,690.51 6766.12,690.51 6770.11,694.5 6912.47,694.5 6933.04,673.94 6933.04,659.43 6948.47,644 6960.97,644 6965.69,639.28 U39.9@6972.87,639.28 U39.2@7005.75,639.28 7012.93,639.28 7016.92,643.28 7030,643.28 7038.3,634.98 7038.3,614.25 7073.24,579.3 7127.85,579.3 7152.19,603.65 7152.19,643.12 J7.6@7189.08,680
ETH1_TD_C_P: J7.5 U22.7 U39.1 U39.10 | length 567
  Bottom Layer w4: U22.7@6759.03,710.2 6766.12,710.2 6770.11,706.2 6917.32,706.2 6944.74,678.78 6944.74,664.27 6953.31,655.7 6962.42,655.7 6965.69,658.97 U39.10@6972.87,658.97 U39.1@7005.75,658.97 7012.93,658.97 7016.92,654.98 7034.85,654.98 7050,639.82 7050,619.09 7078.09,591 7123,591 7140.49,608.5 7140.49,649.48 7134.28,655.7 7114.78,655.7 J7.5@7089.08,630
ETH1_TD_D_N: J7.4 U22.11 U39.5 U39.6 | length 600.5
  Bottom Layer w4: U22.11@6759.03,631.46 6766.12,631.46 6770.11,635.45 6817.1,635.45 6868.33,584.22 6961.69,584.22 6965.69,580.23 U39.6@6972.87,580.23 U39.5@7005.75,580.23 7012.93,580.23 7016.92,584.22 7020.52,584.22 7031.57,573.18 7031.57,516.63 7070.15,478.05 7129.73,478.05 7152.19,500.51 7152.19,543.12 J7.4@7189.08,580
ETH1_TD_D_P: J7.3 U22.10 U39.4 U39.7 | length 600.3
  Bottom Layer w4: U22.10@6759.03,651.14 6766.12,651.14 6770.11,647.15 6821.94,647.15 6873.17,595.92 6961.69,595.92 6965.69,599.91 U39.7@6972.87,599.91 U39.4@7005.75,599.91 7012.93,599.91 7016.92,595.92 7025.37,595.92 7043.27,578.02 7043.27,521.48 7075,489.75 7124.88,489.75 7140.49,505.36 7140.49,546.37 7128.62,558.25 7117.33,558.25 J7.3@7089.08,530
ETH1_TX_CTL_EN: U22.37 U50.15 | length 2083.9
  Top Layer w5.3: U50.15@5303.35,1138.15 v1(5350,1138.15)
  SIG 1 w4.75: v1(5350,1138.15) 5342.66,1130.81 5342.66,875.5 5424.98,793.18 5732.07,793.18 5818.89,706.36 5885.84,706.36 5899.38,719.9 6197.07,719.9 6253.88,663.08 6307.97,663.08 6375.43,730.54 6386.38,730.54 6392.27,724.65 6392.27,704.92 6399.07,698.12 6414.84,698.12 6420.75,704.04 6420.75,768.83 6431.92,780 6450,780 6460,770 6460,658.09 6468.78,649.3 6481.42,649.3 6490.33,658.21 6490.33,705 6500.33,715 6518.83,715 6525,721.17 6525,730.54 6516.85,738.69 6496.65,738.69 6490.33,745 6490.33,765.33 6505,780 v1(6525,780)
  Bottom Layer w5.3: U22.37@6516.91,853.9 6516.91,789.45 6525,781.36 v1(6525,780)
ETH1_TXC: U22.29 U50.16 | length 2089.3
  Top Layer w5.3: U50.16@5303.35,1157.83 5370.31,1157.83 v1(5390,1138.15)
  SIG 1 w4.75: v1(5390,1138.15) 5390,1151.16 5368.07,1173.08 5330.84,1173.08 5320.7,1162.95 5320.7,869.04 5358.65,831.09 5358.65,789.42 5407.98,740.09 5516.32,740.09 5549.32,773.08 5723.75,773.08 5810.57,686.26 5894.16,686.26 5907.7,699.8 6084.38,699.8 6110,674.18 6110,637.01 6122.01,625 6141,625 6150,634 6150,676.6 6156.64,683.24 6185,683.24 6190,678.24 6190,610 6199.95,600.05 6225,600.05 6230,605.05 6230,635 6237.98,642.98 6293.59,642.98 6300,636.57 6300,607.03 6306.98,600.05 6324.29,600.05 6330,605.76 6330,635.11 6351.36,656.47 v1(6415,656.47)
  Bottom Layer w5.3: v1(6415,656.47) 6431.61,656.47 6465.64,690.51 U22.29@6491.32,690.51
ETH1_XI: R117.2 R118.2 U22.20 | length 139
  Bottom Layer w5.3: R118.2@6520,518.62 6588.54,518.62 6595.65,525.73 U22.20@6595.65,586.18
ETH1_XO: R119.2 U22.19 | length 69.5
  Bottom Layer w5.3: U22.19@6615.33,586.18 6615.33,546.87 6620,542.2 R119.2@6620,518.62
ETH1_XTAL_XI: C112.1 R117.1 Y2.1 | length 353.4
  Bottom Layer w5.3: R117.1@6570,471.38 6620,421.38 6712.13,421.38 C112.1@6728.01,405.5 6740.49,405.5 6760.49,385.5 6849.35,385.5 6866.59,402.74 Y2.1@6866.59,416.88
ETH1_XTAL_XO: C113.1 R119.1 Y2.3 | length 221.6
  Bottom Layer w5.3: R119.1@6620,471.38 6620,450.76 6634.18,436.58 6699.09,436.58 C113.1@6728.01,465.5 6729.39,464.12 Y2.3@6802.61,464.12
ETH2_CLKOUT: TP20.1 U37.40 | length 81
  Top Layer w5.3: TP20.1@6555,1797.09 6579.77,1821.86 6579.77,1834.77 v1(6580,1835)
  Bottom Layer w5.3: U37.40@6575.96,1803.9 6575.96,1830.96 v1(6580,1835)
ETH2_GPIO_1: R209.1 R221.2 U37.22 | length 124.8
  Top Layer w5.3: R209.1@6520,1468.62 6570.85,1468.62 R221.2@6570.97,1468.5 6570.97,1493.56 v1(6556.28,1508.25)
  Bottom Layer w5.3: v1(6556.28,1508.25) U37.22@6556.28,1536.18
ETH2_LED0: Q8.1 R233.1 | length 1557.5
  SIG 1 w4.75: v1(6822.8,2000) 6828.75,1994.05 6828.75,1906.25 6850,1885 6850,1380 7053.58,1176.42 7480.55,1176.42 7481.69,1177.57 7487.57,1177.57 v1(7490,1180)
  Bottom Layer w5.3: R233.1@6795,1916.06 6813.2,1916.06 6822.14,1925 6822.14,1999.34 v1(6822.8,2000) ; Q8.1@7471.27,1093.42 7471.27,1161.27 v1(7490,1180)
ETH2_LED1: Q9.1 R235.1 | length 1522.4
  SIG 1 w4.75: v1(6880,1916.06) 6880,1375 7035,1220 7216.02,1220 7235.23,1200.79 7539.21,1200.79 7616.46,1123.54 v1(7616.46,1053.72)
  Bottom Layer w5.3: R235.1@6848,1916.06 v1(6880,1916.06) ; v1(7616.46,1053.72) 7617.73,1055 Q9.1@7617.73,1092.15
ETH2_LED2: Q7.1 R231.1 | length 717.7
  Bottom Layer w5.3: R231.1@6700,2024.37 6700,2070 6855,2225 7164.51,2225 7171.6,2217.92 7296.93,2217.92 Q7.1@7302.6,2212.24
ETH2_PWDN: R306.2 U37.44 | length 96.3
  Top Layer w5.3: R306.2@6620,1876.46 6635.61,1876.46 6647.07,1865 6647.07,1847.93 v1(6655,1840)
  Bottom Layer w5.3: U37.44@6654.7,1803.9 6654.7,1839.7 v1(6655,1840)
ETH2_RBIAS: R202.2 U37.12 | length 78.8
  Bottom Layer w5.3: U37.12@6759.03,1561.77 6759.03,1547.39 6779.43,1526.99 R202.2@6815,1526.99
ETH2_TD_A_N: J8.10 U37.2 U40.2 U40.9 | length 504.6
  Bottom Layer w4: U37.2@6759.03,1758.62 6766.12,1758.62 6770.11,1762.61 6937.42,1762.61 6961.96,1762.61 6965.96,1758.62 U40.9@6973.14,1758.62 U40.2@7006.02,1758.62 7013.2,1758.62 7017.19,1762.61 7124.55,1762.61 7152.19,1790.26 7152.19,1833.12 J8.10@7189.08,1870
ETH2_TD_A_P: J8.9 U37.1 U40.1 U40.10 | length 503.5
  Bottom Layer w4: U37.1@6759.03,1778.31 6766.12,1778.31 6770.11,1774.31 6932.57,1774.31 6961.96,1774.31 6965.96,1778.31 U40.10@6973.14,1778.31 U40.1@7006.02,1778.31 7013.2,1778.31 7017.19,1774.31 7119.71,1774.31 7140.49,1795.1 7140.49,1839.51 7135,1845 7114.08,1845 J8.9@7089.08,1820
ETH2_TD_B_N: J8.8 U37.5 U40.5 U40.6 | length 512.6
  Bottom Layer w4: U37.5@6759.03,1699.57 6766.12,1699.57 6770.11,1703.56 6956.02,1703.56 6961.96,1703.56 6965.96,1699.57 U40.6@6973.14,1699.57 U40.5@7006.02,1699.57 7013.2,1699.57 7017.19,1703.56 7026.57,1703.56 7061.09,1669.04 7124.85,1669.04 7152.19,1696.39 7152.19,1733.12 J8.8@7189.08,1770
